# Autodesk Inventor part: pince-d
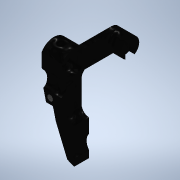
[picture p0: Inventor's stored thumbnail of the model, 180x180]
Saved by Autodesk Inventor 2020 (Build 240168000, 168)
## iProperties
Created: 2023-10
Part Number: pince-d
Material: Générique
Document SubType Name: Modeling
Designer: bruno
Density: 1 g/cm^3
Appearance: Noir
Author: bruno
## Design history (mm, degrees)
sketch "Esquisse1"
  geometry: L1 (-5.917, 4)-(-43.5, 4); L2 (-43.5, 4)-(-43.5, -4); L3 (-43.5, -4)-(-5.917, -4); L4 (-5.917, -4)-(-5.917, 4); C1 r 5 at (0, 0); C2 r 7.5 at (0, 0); 3 further points
  constraints: 8 end point, 2 centre point, 2 coincident, 2 parallel, 1 horizontal, 1 perpendicular
  dimensions: "d0" = 10 diameter of C1; "d1" = 15 diameter of C2; "d2" = 4 distance from line of L3 point (0, 0); "d3" = 4 distance from line of L1 point (0, 0); "d4" = 43.5 distance from line of L2 point (0, 0)
extrude "Extrusion1" new body sketch "Esquisse1" distance "d5" = 15; taper "d6" = 0 deg
sketch "Esquisse2"
  geometry: L1 (15, 37.156)-(15, 0) reference; L2 (0, 0)-(15, 0) reference; L3 (0, 37.156)-(0, 0) reference; L4 (23.715, 19)-(11, 19); L5 (11, 19)-(11, 53.427); L6 (11, 53.427)-(23.715, 53.427); L7 (23.715, 53.427)-(23.715, 19); L8 (15, 0)-(15, 37.156) reference; L9 (15, 0)-(11.265, 1.431); L10 (0, 0)-(0, 37.156) reference; L11 (0, 37.156)-(5.093, 16.193); L12 (5.093, 16.193)-(11.265, 1.431); C1 r 6.035 at (19.697, 7.524); 1 further point
  constraints: 14 end point, 2 parallel, 1 centre point, 1 horizontal, 1 perpendicular
  dimensions: "d7" = 4 distance between parallel lines of L5 L1; "d8" = 19 distance from line of L1.end L4; "d11" = 16 distance of L11.end L9.end; "d12" = 4 distance of L1.end L9.end
extrude "Extrusion2" cut sketch "Esquisse2" stored distance "d9" = 29; taper "d10" = 0 deg
fillet "Congé1" dims "d13" = 4
fillet "Congé2" dims "d14" = 4
sketch "Esquisse3"
  geometry: L1 (-22.111, 12.558)-(-6.5, 12.558); L2 (-6.5, 12.558)-(-6.5, -11.726); L3 (-6.5, -11.726)-(-22.111, -11.726); L4 (-22.111, -11.726)-(-22.111, 12.558); 1 further point
  constraints: 8 end point, 2 parallel, 1 horizontal, 1 perpendicular
  dimensions: "d15" = 6.5 distance from line of L2 point (0, 0)
extrude "Extrusion3" cut sketch "Esquisse3" distance "d16" = 20; taper "d17" = 0 deg
sketch "Esquisse4"
  geometry: L1 (-5.713, 5.5)-(12.395, 5.5); L2 (-3, 8.5)-(-3, 2.5); L3 (0, 0)-(0, 12.239) reference; L4 (-3, 8.5)-(0.406, 8.5); L5 (0.406, 8.5)-(0.406, 2.5); L6 (0.406, 2.5)-(-3, 2.5); L7 (-3, 2.5)-(-3, 8.5); 4 further points
  constraints: 12 end point, 2 horizontal, 2 parallel, 2 perpendicular
  dimensions: "d18" = 15 distance from line of L1 point (4, 20.5); "d19" = 3 distance between parallel lines of L3 L2; "d20" = 3 distance from line of L1 L2.start; "d30" = 3 distance between parallel lines of L1 L6
extrude "Extrusion4" join sketch "Esquisse4" stored distance "d22" = 20; taper "d23" = 0 deg
fillet "Congé3" dims "d24" = 4
sketch "Esquisse5"
  geometry: L1 (-8.168, 0)-(-9.626, 6) reference; L2 (0, 0)-(-8.168, 0) reference; L3 (0, 6)-(0, 0) reference; L4 (0, 6)-(-9.626, 6) reference; L5 (0, 3)-(-8.897, 3); L6 (-5.907, -9.307)-(-10.534, 9.739) reference; C1 r 1.5 at (-6.021, 3); 1 further point
  constraints: 2 end point, 2 point on line, 1 centre point, 1 horizontal, 1 midpoint
  dimensions: "d25" = 3 diameter of C1
extrude "Extrusion5" cut sketch "Esquisse5" distance "d26" = 10; taper "d27" = 0 deg
feature "Filetage1" dims "d28" = 10, "d29" = 0
sketch "Esquisse6"
  geometry: L1 (0.593, 25.5)-(19, 25.5); L2 (19, 25.5)-(19, 15.5); L3 (19, 15.5)-(0.593, 15.5); L4 (-10.5, 24.242)-(-10.5, 16.758) reference; L5 (0.593, 23.852)-(2.525, 19.91); L6 (2.525, 19.91)-(0.593, 16.758); L7 (0.593, 15.5)-(0.593, 16.758); L8 (0.593, 23.852)-(0.593, 25.5); 3 further points
  constraints: 14 end point, 3 parallel, 1 horizontal, 1 midpoint, 1 perpendicular, 3 other
  dimensions: "d31" = 10 distance between parallel lines of L3 L1; "d32" = 5 distance from line of L1 point (-4, 20.5); "d33" = 29.5 distance from line of point (19, 20.5) L4
extrude "Extrusion6" join sketch "Esquisse6" distance "d34" = 3; taper "d35" = 0 deg
sketch "Esquisse7"
  geometry: L1 (-10.5, 24.242)-(-10.5, 16.758) reference; L2 (-11, 8.5)-(-11, 2.5) reference; L3 (0, 0)-(-8.243, 0) reference; L4 (0, 12.239)-(0, 0) reference; L5 (1.59, 15.5)-(19, 15.5) reference; L6 (19, 25.5)-(1.59, 25.5) reference; C1 r 5 at (-4, 20.5) reference; A1 r 7.5 centre (-4, 20.5) between (1.59, 25.5) and (-10.5, 24.242) reference; A2 r 7.5 centre (-4, 20.5) between (-10.5, 16.758) and (-9.287, 15.181) reference; A3 r 4 centre (-12.107, 12.344) between (-11, 8.5) and (-9.287, 15.181) reference; A4 r 4 centre (-12, -1.373) between (-8.243, 0) and (-11, 2.5) reference; A5 r 4 centre (4, 12.239) between (1.217, 15.112) and (0, 12.239) reference; A6 r 7.5 centre (-4, 20.5) between (1.217, 15.112) and (1.59, 15.5) reference; A7 r 5 centre (19, 20.5) between (19, 15.5) and (19, 25.5) reference; A8 r 5 centre (19, 20.5) between (19, 15.5) and (19, 25.5) reference; 3 further points
  constraints: 1 coincident, 3 other
extrude "Extrusion7" join sketch "Esquisse7" distance "d36" = 7; taper "d37" = 0 deg
sketch "Esquisse8"
  geometry: L1 (-2.5, 5.527)-(2.5, 5.527); L2 (2.5, 5.527)-(2.5, -6.119); L3 (2.5, -6.119)-(-2.5, -6.119); L4 (-2.5, -6.119)-(-2.5, 5.527); C1 r 5 at (0, 0) reference; 5 further points
  constraints: 8 end point, 2 parallel, 1 horizontal, 1 perpendicular
  dimensions: "d38" = 2.5 distance from line of L2 C1.centre; "d39" = 2.5 distance from line of L4 C1.centre
extrude "Extrusion8" cut sketch "Esquisse8" distance "d40" = 3; taper "d41" = 0 deg
sketch "Esquisse9"
  geometry: C1 r 1.75 at (0, 0); 1 further point
  constraints: 1 centre point
  dimensions: "d42" = 3.5 diameter of C1
extrude "Extrusion9" cut sketch "Esquisse9" distance "d43" = 10; taper "d44" = 0 deg
node "Solide1"
node "Boucle projetée1"
node "Boucle projetée2"
node "Boucle projetée3"
